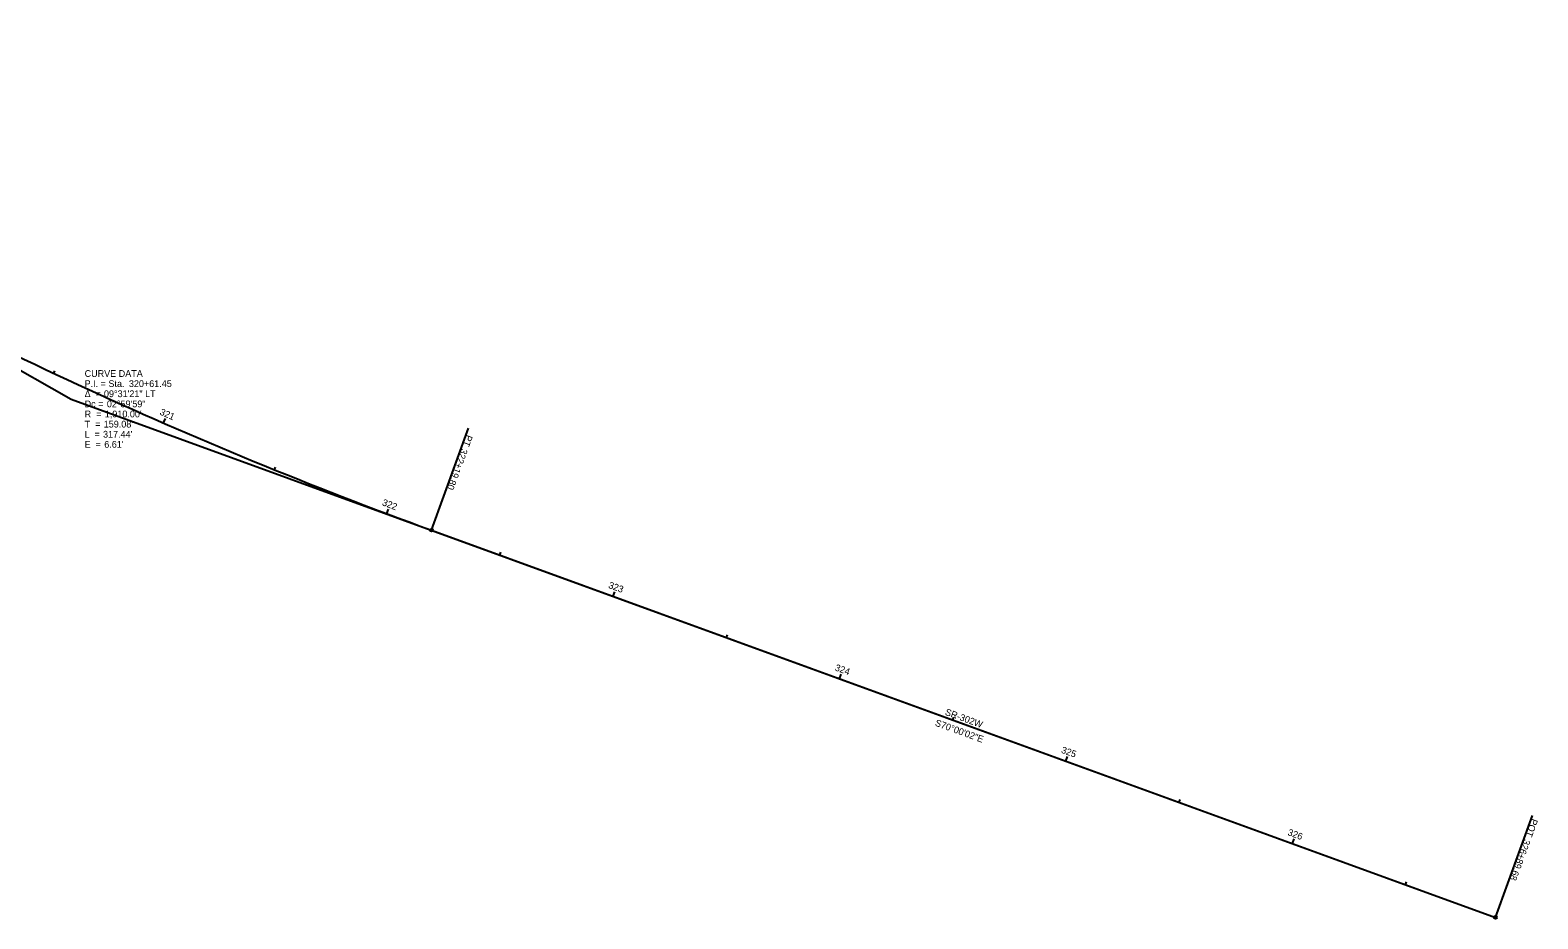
# Model space of a CAD drawing. Extents: x 2047151 to 2048731, y 456453 to 457874.
# Drawn here: x 2048105 to 2048731, y 456601 to 456969 of the extents above; entities that cross this region are included whole.
import ezdxf

# ---------------------------------------------------------------- set-up
doc = ezdxf.new("R2010")
doc.units = 0
for name, color, linetype in [('GE_P_Alignment', 7, 'Continuous'), ('GE_P_Alignment_100_Bearings', 7, 'Continuous'), ('GE_P_Alignment_100_Cardinal_Points', 7, 'Continuous'), ('GE_P_Alignment_100_Curve_Data', 7, 'Continuous'), ('GE_P_Alignment_100_Distances', 7, 'Continuous'), ('GE_P_Alignment_100_Stations', 7, 'Continuous')]:
    doc.layers.add(name, color=color, linetype=linetype)

msp = doc.modelspace()

# ---------------------------------------------------------------- linework, layer by layer
at = {"layer": 'GE_P_Alignment'}
for p, q in [((2047851.96, 456969.42), (2048122.29, 456816.34)), ((2048122.29, 456816.34), (2048713.32, 456601.23)), ((2048271.78, 456761.93), (2048713.32, 456601.23))]:
    msp.add_line(p, q, dxfattribs=at)
msp.add_arc((2048925.02, 458556.75), 1910, 240.47809, 250.00047, dxfattribs=at)
msp.add_arc((2048925.02, 458556.75), 1910, 240.47809, 250.00047, dxfattribs=at)
at = {"layer": 'GE_P_Alignment_100_Cardinal_Points'}
for p, q in [((2048271.78, 456761.93), (2048287.17, 456804.22)), ((2048713.32, 456601.23), (2048728.71, 456643.52))]:
    msp.add_line(p, q, dxfattribs=at)
for centre in [(2048271.78, 456761.93), (2048713.32, 456601.23)]:
    msp.add_circle(centre, 0.6, dxfattribs=at)
at = {"layer": 'GE_P_Alignment_100_Stations'}
for p, q in [((2048115.01, 456827.02), (2048115.52, 456828.11)), ((2048160.56, 456806.41), (2048161.36, 456808.24)), ((2048206.64, 456787), (2048207.09, 456788.11)), ((2048253.21, 456768.8), (2048253.91, 456770.68)), ((2048300.16, 456751.61), (2048300.57, 456752.73)), ((2048347.14, 456734.51), (2048347.83, 456736.38)), ((2048394.13, 456717.4), (2048394.54, 456718.53)), ((2048441.11, 456700.3), (2048441.8, 456702.18)), ((2048488.1, 456683.2), (2048488.51, 456684.33)), ((2048535.08, 456666.1), (2048535.77, 456667.98)), ((2048582.07, 456649), (2048582.48, 456650.13)), ((2048629.05, 456631.9), (2048629.74, 456633.78)), ((2048676.04, 456614.8), (2048676.45, 456615.93))]:
    msp.add_line(p, q, dxfattribs=at)

# ---------------------------------------------------------------- texts
at = {"layer": 'GE_P_Alignment_100_Bearings'}
msp.add_text('S70°00\'02"E', height=2.8, rotation=340.00047, dxfattribs=at).set_placement((2048480.5, 456680.86))
at = {"layer": 'GE_P_Alignment_100_Cardinal_Points'}
for s, p in [('PT', (2048286.31, 456801.72)), ('322+19.80', (2048284.23, 456796)), ('POT', (2048728.37, 456642.45)), ('326+89.68', (2048725.25, 456633.87))]:
    msp.add_text(s, height=2.8, rotation=250.00047, dxfattribs=at).set_placement(p)
at = {"layer": 'GE_P_Alignment_100_Curve_Data'}
for s, p in [('CURVE DATA', (2048127.82, 456825.53)), ('P.I. = Sta. ', (2048127.82, 456821.33)), ('320+61.45', (2048146.19, 456821.33)), ('Δ  = ', (2048127.82, 456817.13)), ('09°31\'21" LT', (2048135.84, 456817.13)), ('Dc = ', (2048127.82, 456812.93)), ('R  = ', (2048127.82, 456808.73)), ("1,910.00'", (2048136.19, 456808.73)), ('02°59\'59"', (2048137.06, 456812.93)), ('T  = ', (2048127.82, 456804.53)), ("159.08'", (2048135.75, 456804.53)), ('L  = ', (2048127.82, 456800.33)), ('E  = ', (2048127.82, 456796.13)), ("317.44'", (2048135.46, 456800.33)), ("6.61'", (2048135.97, 456796.13))]:
    msp.add_text(s, height=2.8, dxfattribs=at).set_placement(p)
at = {"layer": 'GE_P_Alignment_100_Distances'}
msp.add_text('SR-302W', height=2.8, rotation=340.00047, dxfattribs=at).set_placement((2048484.65, 456685.34))
at = {"layer": 'GE_P_Alignment_100_Stations'}
for s, rotation, p in [('321', 336.40674, (2048158.73, 456809.99)), ('322', 339.40652, (2048251.04, 456772.34)), ('323', 340.00047, (2048344.95, 456738.02)), ('324', 340.00047, (2048438.94, 456703.81)), ('325', 340.00047, (2048532.86, 456669.62)), ('326', 340.00047, (2048626.84, 456635.42))]:
    msp.add_text(s, height=2.8, rotation=rotation, dxfattribs=at).set_placement(p)

doc.saveas('drawing.dxf')
